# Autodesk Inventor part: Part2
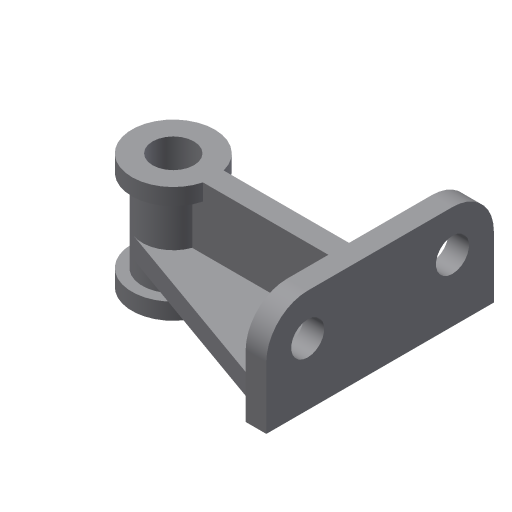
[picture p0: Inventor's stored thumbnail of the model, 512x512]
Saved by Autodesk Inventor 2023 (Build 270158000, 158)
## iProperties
Created: 2001-12
Part Number: Part2
Document SubType Name: Modeling
Density: 1 g/cm^3
Material: Generic
Appearance: Default
Control State: 0
Master: False
Checked Out: False
Shininess: 77.0
Length Units: 11269
Angle Units: 11279
Time Units: 11290
Mass Units: 11283
Length Display Precision: 3
Angle Display Precision: 2
Density: 0.0
Volumn: 0.0
Area: 0.0
PropertySet Name: Model Information
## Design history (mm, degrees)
sketch "Sketch1"
  geometry: L1 (67.049, 55)-(67.049, -55); L2 (60.402, -45.579)-(-27.979, -14.132); L3 (-27.979, 14.132)-(60.402, 45.579); A1 r 10 centre (57.049, -55) between (67.049, -55) and (60.402, -45.579); A2 r 15 centre (-22.951, 0) between (-27.979, 14.132) and (-27.979, -14.132); A3 r 10 centre (57.049, 55) between (60.402, 45.579) and (67.049, 55)
  constraints: 6 end point, 6 point on circle, 6 tangent, 3 centre point, 1 equal length, 1 equal radius, 1 vertical
  dimensions: "d0" = 15 radius of A2; "d1" = 10 radius of A1; "d2" = 90 distance from line of L1 A2.centre; "d3" = 110 distance of L1.start L1.end
extrude "Extrusion1" new body sketch "Sketch1" distance "d4" = 10; taper "d5" = 0 deg
sketch "Sketch2"
  geometry: L1 (0, 110)-(0, 0) reference; L2 (0, 0)-(-30, 0); L3 (-50, 20)-(-50, 90); L4 (-30, 110)-(0, 110); C1 r 8 at (-30, 90); C2 r 8 at (-30, 20); A1 r 20 centre (-30, 20) between (-50, 20) and (-30, 0); A2 r 20 centre (-30, 90) between (-30, 110) and (-50, 90)
  constraints: 6 end point, 4 centre point, 4 point on circle, 4 tangent, 3 perpendicular, 2 coincident, 1 equal radius, 1 parallel
  dimensions: "d6" = 20 radius of A2; "d7" = 50 distance between parallel lines of L1 L3; "d10" = 16 diameter of C1
extrude "Extrusion2" join sketch "Sketch2" distance "d8" = 10; taper "d9" = 0 deg
workplane "Work Plane1"
sketch "Sketch3"
  geometry: C1 r 15 at (-22.951, 0); A1 r 15 centre (-22.951, 0) between (-27.979, 14.132) and (-27.979, -14.132) reference
  constraints: 2 concentric, 1 centre point
extrude "Extrusion3" join sketch "Sketch3" distance "d12" = 56; taper "d13" = 0 deg
sketch "Sketch4"
  geometry: L1 (7.951, 40)-(-57.058, 40); L2 (7.951, 40)-(37.951, 40) reference; L3 (-67.049, 50)-(-67.049, 30) reference; L4 (-77.049, 0)-(-77.049, 30) reference; L5 (-67.049, 0)-(-77.049, 0) reference; A1 r 10 centre (-57.058, 50) between (-67.049, 49.599) and (-57.058, 40)
  constraints: 2 end point, 2 point on circle, 2 point on line, 1 centre point, 1 horizontal, 1 tangent
  dimensions: "d14" = 85 distance from line of L4 L1.start; "d15" = 50 distance from line of L5 A1.centre
feature "Rib1" sketch "Sketch4" dims "d16" = 1, "d17" = 10
sketch "Sketch5"
  geometry: C1 r 20 at (-22.951, 0); 1 further point
  constraints: 1 centre point, 1 coincident
  dimensions: "d18" = 40 diameter of C1
extrude "Extrusion4" join sketch "Sketch5" distance "d19" = 8; taper "d20" = 0 deg
workplane "Work Plane2"
mirror "Mirror1"
sketch "Sketch6"
  geometry: A1 r 20 centre (-22.951, 0) between (-3.586, 5) and (-3.586, -5) reference
hole "Hole1" sketch "Sketch6" at (-22.951, 0) diameter "d22" = 20; stored, may be unused: countersink angle "d26" = 82 deg, drill point angle "d28" = 118 deg; dims "d23" = 6, "d24" = 4, "d25" = 2, "d27" = 8
body "Solid1"
other parameters: "d21" = -28
